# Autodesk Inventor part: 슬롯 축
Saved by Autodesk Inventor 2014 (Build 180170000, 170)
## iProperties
Created: 2025-09
Part Number: 슬롯 축
Material: 일반
Document SubType Name: Modeling
Designer: dg
Density: 1 g/cm^3
Appearance: 기본값
Author: dg
Author: jhkim
Creation Date: 2025-09-02
Sending System: Autodesk Inventor 2026
Preprocessor: ST-DEVELOPER v20.1
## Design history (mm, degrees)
node "슬롯 축1"
node "솔리드1"
node "기준1"
